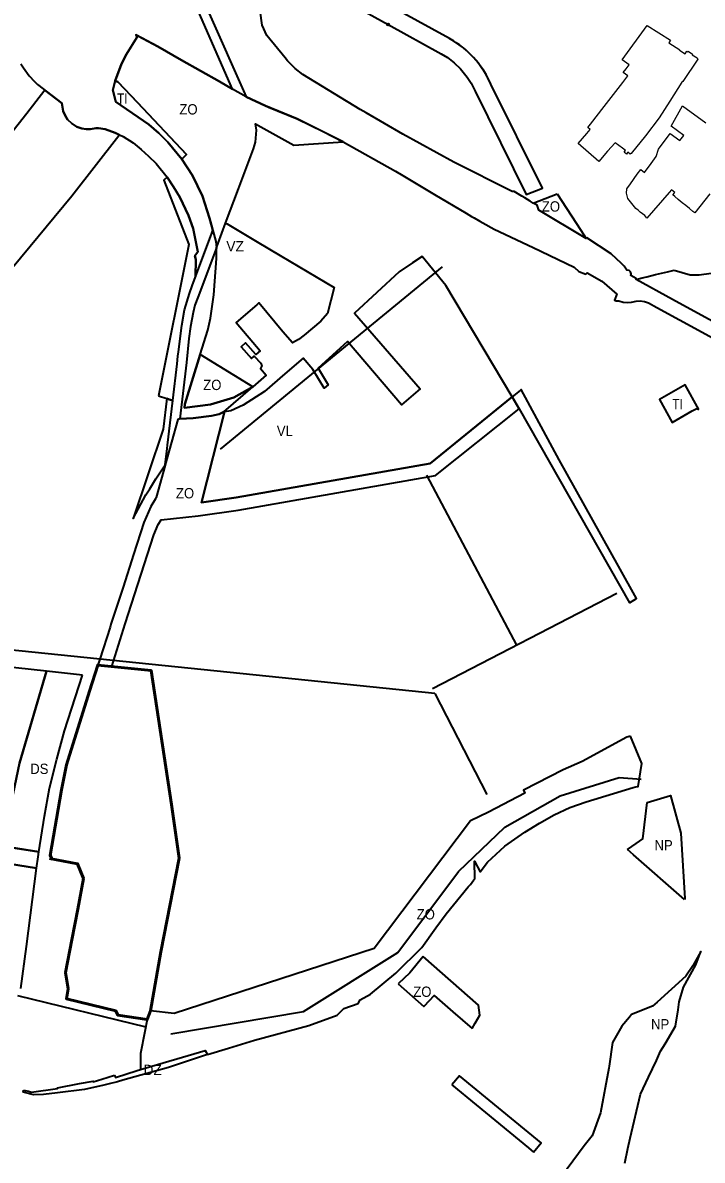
# Model space of a CAD drawing. Extents: x -650276 to -642489, y -1074311 to -1066720.
# Drawn here: x -646730 to -645941, y -1069933 to -1068611 of the extents above; entities that cross this region are included whole.
import ezdxf

# ---------------------------------------------------------------- set-up
doc = ezdxf.new("R2010")
doc.units = 0
doc.header["$LTSCALE"] = 4.8
doc.header["$PDMODE"] = 32
doc.header["$PDSIZE"] = 2.4
for name, color, linetype, lineweight in [('13', 7, 'Continuous', 35), ('15', 7, 'Continuous', 35), ('24', 7, 'Continuous', 35), ('25', 7, 'Continuous', 35), ('30', 7, 'Continuous', 35), ('34', 7, 'Continuous', 35), ('36', 7, 'Continuous', 35), ('42', 7, 'Continuous', 35), ('48', 7, 'Continuous', 35), ('54', 7, 'Continuous', 35), ('60', 7, 'Continuous', 53), ('61', 7, 'Continuous', 25)]:
    doc.layers.add(name, color=color, linetype=linetype, lineweight=lineweight)
doc.layers.add('62', color=7, linetype='Continuous')

msp = doc.modelspace()

# ---------------------------------------------------------------- linework, layer by layer
at = {"layer": '13'}
msp.add_lwpolyline([(-646816.615, -1069558.064), (-646754.066, -1069567.993), (-646733.74, -1069471.688), (-646733.74, -1069471.688), (-646702.425, -1069364.771), (-646702.425, -1069364.771), (-646702.425, -1069364.771), (-646702.425, -1069364.771), (-646702.425, -1069364.771), (-646809.879, -1069353.002), (-646842.103, -1069553.182), (-646842.441, -1069555.283), (-646816.615, -1069558.064)], close=True, dxfattribs=at)
at = {"layer": '15'}
msp.add_line((-646142.68, -1069918.62), (-646136.88, -1069923.39), dxfattribs=at)
for points in [[(-646037.99, -1069242.88), (-646107, -1069119.41), (-646150.87, -1069037.64), (-646152.26, -1069038.76), (-646161.484, -1069046.228), (-646153.307, -1069059.947), (-646025.14, -1069285.394)], [(-646025.14, -1069285.394), (-646017.15, -1069280.19), (-646037.99, -1069242.88)], [(-646755.269, -1069587.04), (-646714.037, -1069593.585), (-646712.34, -1069580.49), (-646711.444, -1069574.771), (-646711.442, -1069574.759), (-646816.615, -1069558.064)], [(-646136.88, -1069923.39), (-646127.987, -1069912.574), (-646222.694, -1069834.722), (-646231.73, -1069845.42)], [(-646231.73, -1069845.42), (-646203.48, -1069868.65), (-646142.68, -1069918.62)]]:
    msp.add_lwpolyline(points, dxfattribs=at)
at = {"layer": '24'}
for points in [[(-646561.544, -1068464.842), (-646553.677, -1068472.283), (-646544.525, -1068479.79), (-646535.245, -1068486.342), (-646523.105, -1068493.54), (-646493.511, -1068509.855), (-646305.678, -1068613.404)], [(-646561.544, -1068464.842), (-646553.677, -1068472.283), (-646544.525, -1068479.79), (-646535.245, -1068486.342), (-646523.105, -1068493.54), (-646493.511, -1068509.855), (-646305.678, -1068613.404)], [(-646234.342, -1068629.893), (-646234.342, -1068629.892), (-646438.626, -1068517.274), (-646513.45, -1068476.025), (-646513.567, -1068475.963)], [(-646234.342, -1068629.893), (-646234.342, -1068629.892), (-646438.626, -1068517.274), (-646513.45, -1068476.025), (-646513.567, -1068475.963)], [(-646337.93, -1068712.4), (-646404.83, -1068671.52), (-646413.45, -1068664.71), (-646422.32, -1068655.58), (-646425.11, -1068652.37), (-646446.54, -1068626.14), (-646451.82, -1068614.31), (-646458.03, -1068569.26)], [(-646634.37, -1068735.27), (-646622.62, -1068739.32), (-646613.44, -1068743.65), (-646601.86, -1068751.01), (-646592.53, -1068758.66), (-646583.98, -1068766.42), (-646575.28, -1068775.04), (-646562.49, -1068790.69), (-646554.8, -1068801.98), (-646547.68, -1068814.22), (-646537.35, -1068835.56), (-646532.16, -1068850.47), (-646526.64, -1068877.47), (-646530.06, -1068882.16), (-646528.92, -1068886.55), (-646529.44, -1068906.81), (-646510.56, -1068855.86), (-646509.323, -1068852.529), (-646513.27, -1068838.37), (-646521.18, -1068812.95), (-646532.92, -1068788.95), (-646545.32, -1068769.89), (-646561.5, -1068750.22), (-646571.91, -1068739.54), (-646583.49, -1068729.76), (-646622.01, -1068703.3), (-646625.35, -1068689.7), (-646622.68, -1068678.75), (-646615.19, -1068659.11), (-646609.7, -1068647.84), (-646597.4, -1068628.74), (-646596.28, -1068626.52), (-646596.28, -1068626.52), (-646573.14, -1068638.98), (-646545.73, -1068654.81), (-646545.73, -1068654.81), (-646501.64, -1068679.81), (-646486.23, -1068688.54), (-646526.1, -1068598.55)], [(-646515.09, -1068597.29), (-646470.65, -1068697.38), (-646448.02, -1068707.99), (-646444.51, -1068709.64), (-646411.3, -1068723.11), (-646380.94, -1068737.81), (-646357.87, -1068749.64), (-646297.08, -1068783.8), (-646288.37, -1068789.04), (-646251.73, -1068811.04), (-646214.92, -1068832.85), (-646208.7, -1068836.39), (-646205.48, -1068838.23), (-646199.24, -1068841.79), (-646195.52, -1068843.92), (-646182.57, -1068851.3)], [(-646305.678, -1068613.404), (-646243.997, -1068647.407), (-646236.707, -1068651.891), (-646228.691, -1068658.051), (-646221.348, -1068665.144), (-646213.659, -1068674.696), (-646209.179, -1068681.795), (-646204.654, -1068690.937), (-646145.083, -1068810.83), (-646126.317, -1068803.654), (-646186.371, -1068682.825)], [(-646305.678, -1068613.404), (-646243.997, -1068647.407), (-646236.707, -1068651.891), (-646228.691, -1068658.051)], [(-646732.25, -1068659.06), (-646729.34, -1068663.94), (-646722.6, -1068673.11), (-646716.39, -1068679.8), (-646716.39, -1068679.8), (-646712.93, -1068683), (-646684.7, -1068704.95), (-646682.98, -1068714.07), (-646680.88, -1068719.28), (-646678.08, -1068723.7), (-646673.16, -1068728.69), (-646667.17, -1068732.38), (-646667.17, -1068732.38), (-646661.5, -1068734.35), (-646656.47, -1068735.13), (-646651.21, -1068734.99), (-646645.18, -1068733.91), (-646642.04, -1068733.74), (-646634.37, -1068735.27)], [(-646228.691, -1068658.051), (-646221.348, -1068665.144), (-646213.659, -1068674.696), (-646209.179, -1068681.795), (-646204.654, -1068690.937), (-646145.083, -1068810.83), (-646126.317, -1068803.654), (-646186.371, -1068682.825)], [(-646741.85, -1068895.719), (-646673.05, -1068812.491), (-646618.655, -1068742.359), (-646617.991, -1068741.503), (-646622.62, -1068739.32), (-646634.37, -1068735.27), (-646642.04, -1068733.74), (-646645.18, -1068733.91), (-646651.21, -1068734.99), (-646656.47, -1068735.13), (-646661.5, -1068734.35), (-646667.17, -1068732.38), (-646673.16, -1068728.69), (-646678.08, -1068723.7), (-646680.88, -1068719.28), (-646682.98, -1068714.07), (-646684.7, -1068704.95), (-646704.316, -1068689.698), (-646725.374, -1068716.786), (-646751.116, -1068749.975)], [(-645933.28, -1068955.74), (-645975.31, -1068932.8), (-646017.55, -1068909.75), (-646017.39, -1068908.42), (-646023.56, -1068905.05), (-646023.13, -1068903.12), (-646023.92, -1068900.73), (-646025.57, -1068899.39), (-646028.18, -1068898.89), (-646031.31, -1068894.32), (-646034.65, -1068891.12), (-646046.48, -1068879.92), (-646074.78, -1068861.51), (-646075.56, -1068861.95), (-646130.68, -1068829.21), (-646132.62, -1068823.54), (-646136.99, -1068820.88), (-646140.73, -1068818.61), (-646146.85, -1068814.88), (-646150.26, -1068812.81), (-646159.1, -1068807.43), (-646161.45, -1068807.54), (-646229.44, -1068773.53), (-646288.59, -1068740.88), (-646331.26, -1068716.25), (-646337.93, -1068712.4)], [(-646182.57, -1068851.3), (-646137.23, -1068872.6), (-646089.63, -1068895.5), (-646084.1, -1068900.51), (-646076.09, -1068903.48), (-646074.51, -1068901.9), (-646057.13, -1068911.62), (-646039.84, -1068926.67), (-646042.5, -1068933.91), (-646040.65, -1068934.59), (-646037.5, -1068934.7), (-646032.61, -1068936.1), (-646027.69, -1068936.6), (-646022.77, -1068936.12), (-646017.6, -1068934.89), (-646012.64, -1068934.34), (-646007.7, -1068935.18), (-646002.95, -1068936.95), (-645993.5, -1068942.1), (-645940.77, -1068970.74), (-645896.91, -1068994.75)], [(-646505.17, -1068872.78), (-646526.81, -1068930.69), (-646530.08, -1068939.43), (-646532.13, -1068948), (-646535.13, -1068964.38), (-646537.02, -1068978.44), (-646539.77, -1069006.25), (-646547.412, -1069071.71), (-646532, -1069071)], [(-646505.17, -1068872.78), (-646526.81, -1068930.69), (-646530.08, -1068939.43), (-646532.13, -1068948), (-646535.13, -1068964.38), (-646537.02, -1068978.44), (-646539.77, -1069006.25)], [(-646524, -1068997), (-646514.91, -1068968.48), (-646514.91, -1068968.48), (-646512.07, -1068954.68), (-646507.91, -1068927.47), (-646505.12, -1068885.31), (-646505.17, -1068872.78)], [(-646524, -1068997), (-646514.91, -1068968.48), (-646514.91, -1068968.48), (-646512.07, -1068954.68), (-646507.91, -1068927.47), (-646505.12, -1068885.31), (-646505.17, -1068872.78)], [(-646462.98, -1069034.61), (-646485, -1069047), (-646512, -1069055), (-646542, -1069059), (-646541.71, -1069054.76), (-646524, -1068997)], [(-646512, -1069055), (-646542, -1069059), (-646541.71, -1069054.76), (-646524, -1068997)], [(-646539.77, -1069006.25), (-646539.77, -1069006.25), (-646547.412, -1069071.71)], [(-646547.412, -1069071.71), (-646532, -1069071), (-646511, -1069068), (-646502, -1069066), (-646496.317, -1069063.61), (-646462.98, -1069034.61)], [(-646532, -1069071), (-646511, -1069068), (-646502, -1069066), (-646496.317, -1069063.61), (-646462.98, -1069034.61), (-646485, -1069047), (-646512, -1069055)], [(-646725.82, -1069684.5), (-646714.037, -1069593.585), (-646755.269, -1069587.04), (-646772.907, -1069727.177)], [(-646732.143, -1069733.308), (-646725.82, -1069684.5), (-646725.82, -1069684.5)]]:
    msp.add_lwpolyline(points, dxfattribs=at)
for points in [[(-646582.46, -1069152.81), (-646575.4, -1069141.46), (-646564.54, -1069125.08), (-646562.35, -1069106.21), (-646561.88, -1069102.18), (-646555.84, -1069050.22), (-646555.84, -1069050.22), (-646559.8, -1069048.98), (-646562.61, -1069048.08), (-646566.82, -1069083.62), (-646601.82, -1069187.25), (-646586.97, -1069160.06), (-646585.42, -1069157.56), (-646583.89, -1069155.1), (-646582.46, -1069152.81)], [(-646660.526, -1069369.36), (-646702.425, -1069364.771), (-646733.74, -1069471.688), (-646754.066, -1069567.993), (-646711.442, -1069574.759), (-646704.68, -1069533.06), (-646699.07, -1069500.57), (-646690.51, -1069466.97), (-646681.5, -1069434.17)]]:
    msp.add_lwpolyline(points, close=True, dxfattribs=at)
for start, end in [(23.23727, 61.13296), (57.43148, 61.13296), (23.23727, 57.43149)]:
    msp.add_arc((-646287.447, -1068726.224), 110, start, end, dxfattribs=at)
msp.add_point((-646305.678, -1068613.404), dxfattribs=at)
at = {"layer": '25'}
msp.add_line((-646729.54, -1069853.69), (-646729.24, -1069851.41), dxfattribs=at)
for points in [[(-646515.63, -1069810.24), (-646522.32, -1069812.28), (-646560.92, -1069825.33), (-646613.65, -1069840.02), (-646620.06, -1069841.69), (-646629.83, -1069844.23), (-646635.93, -1069845.82), (-646658.5, -1069850.59), (-646689.73, -1069854.58), (-646705.87, -1069856.62), (-646717.66, -1069857.11), (-646729.54, -1069853.69)], [(-646593.34, -1069827.68), (-646518.19, -1069805.27), (-646515.63, -1069810.24)], [(-646729.24, -1069851.41), (-646723.5, -1069852.83), (-646719.82, -1069853.78), (-646689.63, -1069849.7), (-646689.8, -1069848.71), (-646664.22, -1069843.72), (-646648.18, -1069841.04), (-646648.28, -1069841.78), (-646638.34, -1069838.73), (-646623.31, -1069834.1)], [(-646623.31, -1069834.1), (-646622.54, -1069835.88), (-646622.19, -1069836.71), (-646597.29, -1069828.86), (-646593.34, -1069827.68)]]:
    msp.add_lwpolyline(points, dxfattribs=at)
at = {"layer": '30'}
msp.add_line((-646583.49, -1068729.76), (-646571.91, -1068739.54), dxfattribs=at)
for points in [[(-646571.91, -1068739.54), (-646561.5, -1068750.22), (-646545.32, -1068769.89), (-646539.78, -1068764.65), (-646596.93, -1068704.15), (-646619.74, -1068680.15), (-646622.68, -1068678.75), (-646625.35, -1068689.7)], [(-646625.35, -1068689.7), (-646622.01, -1068703.3), (-646583.49, -1068729.76)], [(-646562.49, -1068790.69), (-646566.34, -1068794.32), (-646537.3, -1068868.95), (-646572.42, -1069044.94)], [(-646526.64, -1068877.47), (-646532.16, -1068850.47), (-646537.35, -1068835.56), (-646547.68, -1068814.22), (-646554.8, -1068801.98), (-646562.49, -1068790.69)], [(-646529.44, -1068906.81), (-646528.92, -1068886.55), (-646530.06, -1068882.16), (-646526.64, -1068877.47)], [(-646555.84, -1069050.22), (-646550.89, -1069007.7), (-646549.81, -1068998.88), (-646549.17, -1068993.71), (-646545.42, -1068963.3), (-646542.16, -1068945.12), (-646536.54, -1068925.95), (-646533.28, -1068917.17), (-646529.44, -1068906.81)], [(-645944.69, -1069060.7), (-645960.67, -1069032.26), (-645990.13, -1069049.3), (-645975.48, -1069075.71), (-645952.21, -1069062.4)], [(-646572.42, -1069044.94), (-646562.61, -1069048.08), (-646559.8, -1069048.98), (-646555.84, -1069050.22)], [(-645952.21, -1069062.4), (-645946.84, -1069059.58), (-645944.69, -1069060.7)]]:
    msp.add_lwpolyline(points, dxfattribs=at)
msp.add_lwpolyline([(-645944.69, -1069060.7), (-645960.67, -1069032.26), (-645990.13, -1069049.3), (-645975.48, -1069075.71), (-645952.21, -1069062.4), (-645946.84, -1069059.58)], close=True, dxfattribs=at)
at = {"layer": '34'}
msp.add_lwpolyline([(-646161.484, -1069046.228), (-646238.632, -1068916.799), (-646266.118, -1068883.048), (-646277.268, -1068890.446), (-646292.75, -1068900.72), (-646344.49, -1068948.736), (-646268.528, -1069036.82), (-646290.099, -1069055.423), (-646352.71, -1068981.82), (-646386.936, -1069012.936), (-646375.346, -1069032.07), (-646379.973, -1069035.889), (-646393.09, -1069014.234), (-646404.269, -1069001.033), (-646425.52, -1069019.41), (-646449.418, -1069039.804), (-646474.13, -1069055.83), (-646488.537, -1069062.169), (-646495.89, -1069063.531), (-646522.35, -1069168.648), (-646482.211, -1069162.813), (-646256.824, -1069123.414)], close=True, dxfattribs=at)
at = {"layer": '36'}
msp.add_lwpolyline([(-646512.07, -1068954.68), (-646507.91, -1068927.47), (-646505.12, -1068885.31), (-646505.17, -1068872.78), (-646503.24, -1068867.61), (-646494.52, -1068844.29), (-646492.73, -1068845.01), (-646457.86, -1068865.8), (-646430.86, -1068881.89), (-646368.3, -1068919.19), (-646376.02, -1068949.34), (-646383.86, -1068958.24), (-646403.13, -1068974.41), (-646409.67, -1068979.3), (-646416.71, -1068983.21), (-646427.77, -1068970.39), (-646455.78, -1068936.87), (-646458.21, -1068938.99), (-646482.2, -1068959.52), (-646454.21, -1068992.73), (-646459.25, -1068996.98), (-646471.24, -1068983.41), (-646476.35, -1068987.98), (-646464.24, -1069001.49), (-646461.29, -1068998.81), (-646453.48, -1069006.75), (-646452.37, -1069010.01), (-646453.88, -1069013.1), (-646447.2, -1069020.9), (-646462.98, -1069034.61), (-646524, -1068997), (-646514.91, -1068968.48), (-646514.91, -1068968.48)], close=True, dxfattribs=at)
at = {"layer": '42'}
msp.add_line((-646230.3, -1069760.5), (-646208.135, -1069779.937), dxfattribs=at)
for points in [[(-646609.7, -1068647.84), (-646615.19, -1068659.11), (-646622.68, -1068678.75), (-646619.74, -1068680.15), (-646596.93, -1068704.15), (-646539.78, -1068764.65), (-646545.32, -1068769.89), (-646532.92, -1068788.95), (-646521.18, -1068812.95), (-646513.27, -1068838.37), (-646505.69, -1068865.56), (-646505.17, -1068872.78), (-646503.24, -1068867.61), (-646494.52, -1068844.29), (-646479.45, -1068804.37), (-646461.92, -1068757.93), (-646459.59, -1068750.19), (-646458.57, -1068736.31), (-646459.54, -1068728.94), (-646453.51, -1068732.3), (-646415.3, -1068753.62), (-646357.87, -1068749.64), (-646411.3, -1068723.11), (-646448.02, -1068707.99), (-646470.65, -1068697.38), (-646486.23, -1068688.54), (-646501.64, -1068679.81), (-646545.73, -1068654.81), (-646573.14, -1068638.98), (-646598.59, -1068625.34), (-646597.4, -1068628.74)], [(-646541.71, -1069054.76), (-646542, -1069059), (-646512, -1069055), (-646485, -1069047), (-646462.98, -1069034.61), (-646524, -1068997)], [(-646522.35, -1069168.648), (-646495.89, -1069063.531), (-646496.317, -1069063.61), (-646496.317, -1069063.61), (-646502, -1069066), (-646511, -1069068), (-646532, -1069071), (-646547.412, -1069071.71), (-646549.91, -1069072.542), (-646564.54, -1069125.08), (-646564.605, -1069125.271), (-646574.978, -1069163.017), (-646574.978, -1069163.017), (-646574.33, -1069162.04), (-646575.87, -1069164.54), (-646581.29, -1069173.32), (-646589.56, -1069192.07), (-646601.41, -1069229.34), (-646613.6, -1069267.04), (-646627.59, -1069310.34), (-646628.66, -1069313.66), (-646640.715, -1069350.951), (-646642.89, -1069357.68), (-646626.774, -1069359.349), (-646611.107, -1069309.68), (-646577.878, -1069206.485), (-646572.586, -1069194.485), (-646569.114, -1069188.86), (-646526.31, -1069184.381), (-646479.84, -1069177.626), (-646250.409, -1069137.52), (-646153.307, -1069059.947), (-646161.484, -1069046.228), (-646256.824, -1069123.414), (-646482.211, -1069162.813)]]:
    msp.add_lwpolyline(points, close=True, dxfattribs=at)
for points in [[(-646075.56, -1068861.95), (-646130.68, -1068829.21), (-646132.62, -1068823.54), (-646136.99, -1068820.88), (-646109.35, -1068810.23)], [(-646109.35, -1068810.23), (-646081.72, -1068852.51), (-646075.56, -1068861.95)], [(-646017.55, -1068909.75), (-646010.48, -1068907.86), (-646004.88, -1068906.5), (-645994.9, -1068904.1), (-645980.93, -1068900.85), (-645973.36, -1068898.93)], [(-645856.26, -1068997.79), (-645892.77, -1068977.86), (-645933.28, -1068955.74), (-645975.31, -1068932.8), (-646017.55, -1068909.75)], [(-645973.36, -1068898.93), (-645954.59, -1068904.41), (-645944.23, -1068904.13), (-645930.1, -1068902.47), (-645915.61, -1068901.02), (-645902.91, -1068901.43), (-645882.63, -1068905.88), (-645856.26, -1068997.79)], [(-646023.96, -1069440.34), (-646028.16, -1069441.58), (-646080.35, -1069469.89), (-646102.15, -1069479.49), (-646148.5, -1069503), (-646146.8, -1069506.6), (-646189.17, -1069528.74), (-646209.9, -1069538.5), (-646321.973, -1069686.855), (-646554.262, -1069762.602), (-646581.489, -1069759.421), (-646585.51, -1069769.57)], [(-646017.63, -1069499.08), (-646017.63, -1069499.08), (-646015.16, -1069498.74), (-646010.65, -1069471.91), (-646023.96, -1069440.34)], [(-646491.18, -1069802.78), (-646491.18, -1069802.78), (-646460.97, -1069793.56), (-646397.74, -1069776.29), (-646364.67, -1069764.23), (-646357, -1069756.7), (-646340.48, -1069750.92), (-646337.97, -1069746.4), (-646325.92, -1069740.05), (-646296.64, -1069715.72), (-646266.27, -1069685.75), (-646250, -1069663.09), (-646238.19, -1069646.63), (-646212.43, -1069615.33), (-646210.03, -1069612.42), (-646205.9, -1069607.17), (-646205, -1069606.03), (-646205.25, -1069585.67), (-646198.82, -1069597.83), (-646190.07, -1069586.48), (-646169.9, -1069568.04), (-646146.81, -1069551.97), (-646129.87, -1069541.19), (-646112.56, -1069531.78), (-646094.39, -1069523.34), (-646075.48, -1069516.38), (-646020.75, -1069500), (-646017.63, -1069499.08)], [(-646265.02, -1069696.43), (-646280.5, -1069715.27), (-646293.76, -1069728)], [(-646208.135, -1069779.937), (-646204.6, -1069773.78), (-646199.17, -1069764.33), (-646200.67, -1069752.88), (-646265.02, -1069696.43)], [(-646293.76, -1069728), (-646263.929, -1069754.309), (-646263.36, -1069753.69), (-646252.07, -1069741.41), (-646230.3, -1069760.5)], [(-646585.51, -1069769.57), (-646588.25, -1069783.37), (-646593.34, -1069808.99), (-646593.34, -1069827.68)], [(-646593.34, -1069827.68), (-646518.19, -1069805.27), (-646515.63, -1069810.24), (-646491.18, -1069802.78)]]:
    msp.add_lwpolyline(points, dxfattribs=at)
at = {"layer": '48'}
for points in [[(-646027.49, -1069571.79), (-646017.39, -1069564.94), (-646009.52, -1069559.6), (-646004.7, -1069517.16)], [(-646004.7, -1069517.16), (-645977.73, -1069509.11), (-645965.36, -1069552.99), (-645960.78, -1069628.91), (-645961.36, -1069630.05)], [(-645961.36, -1069630.05), (-646020.4, -1069578.04), (-646027.49, -1069571.79)], [(-646030.62, -1069936.3), (-646027.3, -1069919.47), (-646024.41, -1069907.23), (-646012.37, -1069856.22), (-646003.18, -1069836.56), (-645993.96, -1069817.23), (-645989.01, -1069806.25), (-645983.89, -1069797.86), (-645971.7, -1069777.05), (-645968.78, -1069758.13), (-645967.35, -1069748.81), (-645962.48, -1069732.04), (-645948.22, -1069705.79), (-645942.41, -1069690.26), (-645951.52, -1069707.28), (-645959.63, -1069718.95), (-645993.22, -1069749.24), (-645998.57, -1069754.06), (-646022.72, -1069763.59), (-646025.11, -1069766.63), (-646034.02, -1069777.19), (-646044.94, -1069796.35), (-646048.71, -1069823.79), (-646049, -1069825.93), (-646058.71, -1069877.82), (-646068.5, -1069904.5), (-646077.78, -1069916.11), (-646104.04, -1069951.75)]]:
    msp.add_lwpolyline(points, dxfattribs=at)
at = {"layer": '54'}
for p, q in [((-646500.355, -1069106.714), (-646242.413, -1068894.833)), ((-646261, -1069137), (-646156.539, -1069334.511)), ((-646253.953, -1069385.091), (-646040, -1069274)), ((-646251.153, -1069390.558), (-647038.68, -1069310.312)), ((-646251.153, -1069390.558), (-646191, -1069508)), ((-646736.301, -1069741.493), (-646587.205, -1069778.112))]:
    msp.add_line(p, q, dxfattribs=at)
msp.add_lwpolyline([(-646558.043, -1069786.029), (-646403.749, -1069760.313), (-646294.458, -1069691.739), (-646223.741, -1069597.448), (-646170.167, -1069546.017), (-646105.878, -1069509.587), (-646037.303, -1069488.157), (-646011.588, -1069490.3)], dxfattribs=at)
at = {"layer": '60'}
msp.add_lwpolyline([(-646695.61, -1069583.8), (-646698.4, -1069578.93), (-646684.95, -1069502.53), (-646679.13, -1069473.51), (-646652.72, -1069388.08), (-646642.89, -1069357.68), (-646580.797, -1069364.111), (-646557.39, -1069519.61), (-646548.41, -1069582.03), (-646569.86, -1069690.67), (-646581.489, -1069759.421), (-646585.51, -1069769.57), (-646619.49, -1069764.46), (-646622, -1069759.34), (-646679.46, -1069745.37), (-646677.36, -1069733.65), (-646680.28, -1069714.83), (-646673, -1069676.8), (-646666.26, -1069641.2), (-646659.52, -1069605.53), (-646666.36, -1069588.57), (-646698.96, -1069582.26)], dxfattribs=at)
at = {"layer": '61'}
msp.add_lwpolyline([(-645977.65, -1068631.85), (-645979.52, -1068634.8), (-645966.82, -1068642.9), (-645967.14, -1068643.41), (-645960.63, -1068647.57), (-645958.67, -1068644.5), (-645957.36, -1068645.33), (-645956.91, -1068644.61), (-645951.87, -1068647.86), (-645952.28, -1068648.55), (-645946.37, -1068652.24), (-645945.75, -1068653.7), (-645963.17, -1068679.86), (-645964.19, -1068680.5), (-645978.4, -1068702.69), (-645990.79, -1068722.02), (-646006.77, -1068742.76), (-646023.16, -1068763.37), (-646024.22, -1068764.13), (-646027.21, -1068761.88), (-646028.77, -1068763.95), (-646031.47, -1068761.91), (-646029.91, -1068759.84), (-646033.21, -1068757.35), (-646041.889, -1068750.882), (-646050.57, -1068760.83), (-646060.78, -1068772.53), (-646084.74, -1068751.8), (-646074.61, -1068740.08), (-646070.697, -1068735.553), (-646073.6, -1068733.3), (-646070.57, -1068729.39), (-646054.6, -1068708.79), (-646033.02, -1068680.97), (-646027.29, -1068673.19), (-646032.35, -1068669.34), (-646028.98, -1068664.82), (-646025.68, -1068660.38), (-646033.67, -1068654.56), (-646004.63, -1068614.59)], close=True, dxfattribs=at)
msp.add_lwpolyline([(-645931.74, -1068810.06), (-645949.45, -1068832.34), (-645951.53, -1068830.71), (-645955.59, -1068827.42), (-645959.81, -1068823.96), (-645964.09, -1068820.54), (-645968.55, -1068816.88), (-645972.63, -1068813.49), (-645974.79, -1068811.55), (-645972.63, -1068808.55), (-645976.52, -1068805.7), (-645979.15, -1068808.68), (-646005.18, -1068838.43), (-646007.27, -1068835.51), (-646009.97, -1068833.45), (-646012.63, -1068831.33), (-646015.29, -1068829.21), (-646017.95, -1068827.09), (-646027.13, -1068815.63), (-646028.59, -1068809.26), (-646028.24, -1068804.53), (-646023.94, -1068798.68), (-646016.36, -1068787.54), (-646012.15, -1068781.94), (-646007.68, -1068785.56), (-646000.11, -1068774.8), (-645994.29, -1068767.03), (-645991.63, -1068758.23), (-645977.81, -1068739.99), (-645966.626, -1068748.419), (-645962.14, -1068742.51), (-645976.82, -1068731.5), (-645963.52, -1068707.92), (-645936.46, -1068727.71)], dxfattribs=at)

# ---------------------------------------------------------------- texts
at = {"layer": '62'}
for s, width, p in [('TI', 0.85, (-646620.476, -1068705.535)), ('ZO', 0.95, (-646548.118, -1068718.035)), ('ZO', 0.95, (-646127.027, -1068830.859)), ('ZO', 0.95, (-646520.423, -1069038.188)), ('TI', 0.85, (-645975.476, -1069060.535)), ('VL', 0.95, (-646434.928, -1069091.6)), ('ZO', 0.95, (-646552.118, -1069164.035)), ('DS', 0.95, (-646721.423, -1069484.188)), ('NP', 0.95, (-645996.15, -1069572.972)), ('ZO', 0.95, (-646272.423, -1069653.188)), ('ZO', 0.95, (-646276.423, -1069743.188)), ('NP', 0.95, (-646000.15, -1069780.972))]:
    msp.add_text(s, height=12, dxfattribs=dict(at, width=width)).set_placement(p)
for s, p in [('VZ', (-646493.598, -1068877.069)), ('DZ', (-646589.843, -1069833.949))]:
    msp.add_text(s, height=12, dxfattribs=at).set_placement(p)

doc.saveas('drawing.dxf')
